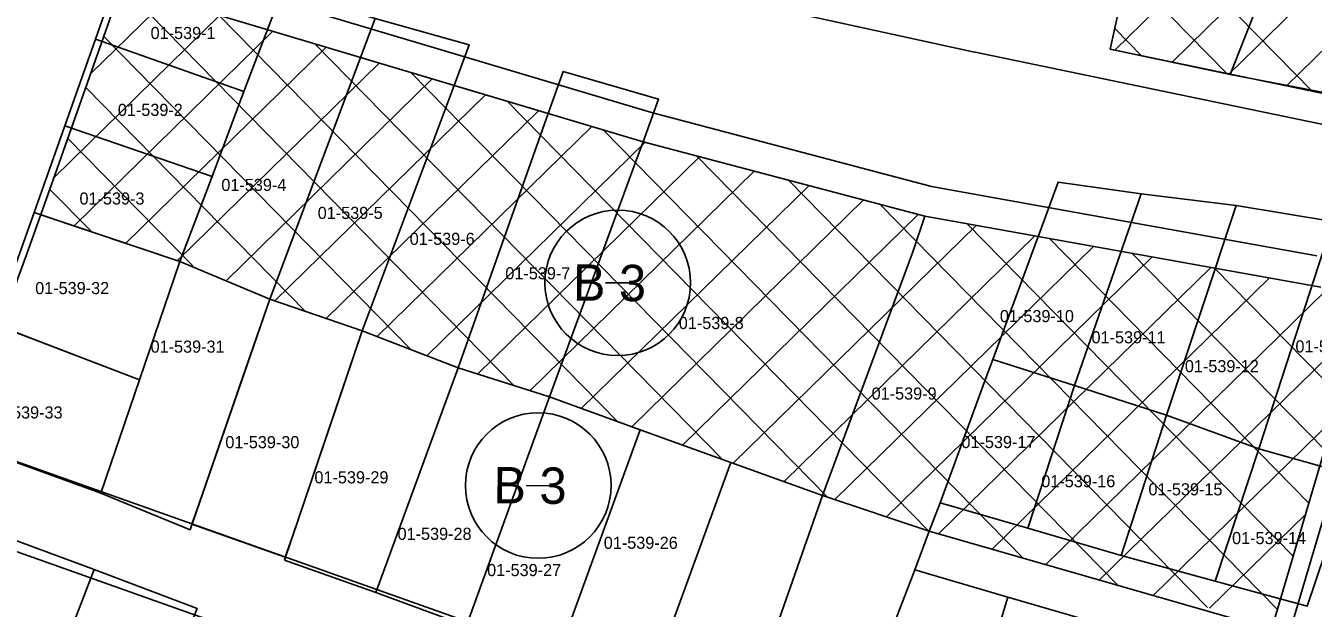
# Model space of a CAD drawing. Extents: x 413946 to 415528, y 4453939 to 4454944.
# Drawn here: x 415070.8 to 415176.9, y 4454376.6 to 4454424.6 of the extents above; entities that cross this region are included whole.
import ezdxf

# ---------------------------------------------------------------- set-up
doc = ezdxf.new("R2010")
doc.units = 0
for name, color, linetype in [('0_KADASTRO', 7, 'Continuous'), ('Level 27', 7, 'Continuous'), ('Level 29', 7, 'Continuous'), ('Level 32', 7, 'Continuous'), ('Level 34', 7, 'Continuous'), ('Level 57', 7, 'Continuous'), ('Level 62', 7, 'Continuous')]:
    doc.layers.add(name, color=color, linetype=linetype)

msp = doc.modelspace()

# ---------------------------------------------------------------- linework, layer by layer
at = {"layer": '0_KADASTRO'}
for points in [[(415160.16, 4454422.69), (415162.75, 4454434.4), (415165.76, 4454447.93), (415177.83, 4454443.03), (415178.24, 4454442.84), (415178.86, 4454442.55), (415176.37, 4454436.61), (415174.78, 4454432.63), (415170.05, 4454420.62)], [(415170.05, 4454420.62), (415174.78, 4454432.63), (415176.37, 4454436.61), (415178.86, 4454442.55), (415187.02, 4454438.74), (415184.58, 4454432.79), (415178.92, 4454418.9)], [(415076.56, 4454423.51), (415079.21, 4454431.05), (415091.94, 4454427.51), (415088.79, 4454419.21)], [(415083.5, 4454405.19), (415086.16, 4454412.19), (415088.79, 4454419.21), (415091.94, 4454427.51), (415099.59, 4454425.23), (415090.92, 4454402.08)], [(415090.92, 4454402.08), (415099.59, 4454425.23), (415107.35, 4454423.05), (415106.1, 4454419.71), (415098.53, 4454399.46)], [(415074.02, 4454416.38), (415076.56, 4454423.51), (415088.79, 4454419.21), (415086.16, 4454412.19)], [(415106.43, 4454396.4), (415113.86, 4454417.39), (415115.09, 4454420.86), (415122.95, 4454418.57), (415121.68, 4454415.05), (415121.13, 4454413.59), (415113.97, 4454394.01)], [(415098.53, 4454399.46), (415106.1, 4454419.71), (415113.86, 4454417.39), (415106.43, 4454396.4)], [(415071.51, 4454409.23), (415074.02, 4454416.38), (415086.16, 4454412.19), (415083.5, 4454405.19)], [(415113.97, 4454394.01), (415121.13, 4454413.59), (415121.68, 4454415.05), (415144.9, 4454408.93), (415143.87, 4454405.91), (415136.45, 4454385.89), (415128.92, 4454388.61), (415121.44, 4454391.29)], [(415150.5, 4454397.11), (415154.24, 4454407.25), (415154.36, 4454407.59), (415155.89, 4454411.73), (415162.73, 4454410.76), (415157.23, 4454394.94)], [(415157.23, 4454394.94), (415162.73, 4454410.76), (415170.55, 4454409.79), (415164.81, 4454392.51)], [(415068.21, 4454400.01), (415071.51, 4454409.23), (415083.5, 4454405.19), (415080.18, 4454395.43)], [(415164.81, 4454392.51), (415170.55, 4454409.79), (415178.51, 4454408.47), (415172.41, 4454389.72)], [(415136.45, 4454385.89), (415143.87, 4454405.91), (415144.9, 4454408.93), (415153.94, 4454407.3), (415154.24, 4454407.25), (415150.5, 4454397.11), (415150.12, 4454396.08), (415146.16, 4454385.28), (415145.24, 4454382.95)], [(415172.41, 4454389.72), (415178.51, 4454408.47), (415186.56, 4454407.48), (415180.05, 4454387.58)], [(415077.01, 4454386.07), (415080.18, 4454395.43), (415083.5, 4454405.19), (415090.92, 4454402.08), (415084.35, 4454383.06)], [(415084.51, 4454383.52), (415085.1, 4454385.22), (415088.71, 4454395.68), (415090.92, 4454402.08), (415098.53, 4454399.46), (415096.35, 4454393.02), (415092.78, 4454382.49), (415092.2, 4454380.79)], [(415068.7, 4454399.82), (415065.19, 4454390.35), (415077.01, 4454386.07), (415080.18, 4454395.43)], [(415092.12, 4454380.54), (415098.53, 4454399.46), (415106.43, 4454396.4), (415099.65, 4454377.88)], [(415099.65, 4454377.88), (415106.43, 4454396.4), (415113.97, 4454394.01), (415107.23, 4454375.45), (415107.12, 4454375.14)], [(415146.16, 4454385.28), (415150.12, 4454396.08), (415150.5, 4454397.11), (415157.23, 4454394.94), (415153.38, 4454383.19)], [(415153.38, 4454383.19), (415157.23, 4454394.94), (415164.81, 4454392.51), (415161.06, 4454380.94)], [(415107.23, 4454375.45), (415113.97, 4454394.01), (415121.44, 4454391.29), (415114.71, 4454372.79)], [(415161.06, 4454380.94), (415164.81, 4454392.51), (415172.41, 4454389.72), (415168.83, 4454378.8)], [(415114.54, 4454372.33), (415114.71, 4454372.79), (415121.44, 4454391.29), (415128.92, 4454388.61), (415122.05, 4454369.73)], [(415168.83, 4454378.8), (415172.41, 4454389.72), (415180.05, 4454387.58), (415176.39, 4454376.74)], [(415122.05, 4454369.73), (415128.92, 4454388.61), (415136.45, 4454385.89), (415129.86, 4454367.05)], [(415129.86, 4454367.05), (415136.45, 4454385.89), (415145.24, 4454382.95), (415144.06, 4454379.75), (415140.81, 4454371.26), (415138.05, 4454364.04)], [(415059.75, 4454375.97), (415062.85, 4454384.81), (415076.46, 4454379.78), (415073.1, 4454371.06)], [(415071.73, 4454367.47), (415073.1, 4454371.06), (415076.46, 4454379.78), (415084.93, 4454376.57), (415080.1, 4454364.35)], [(415140.81, 4454371.26), (415144.06, 4454379.75), (415151.74, 4454377.5), (415149.1, 4454368.79), (415144.42, 4454370.19)], [(415149.1, 4454368.79), (415151.74, 4454377.5), (415167.07, 4454373.03), (415164.65, 4454364.98), (415160.35, 4454365.95), (415156.93, 4454366.72)]]:
    msp.add_lwpolyline(points, close=True, dxfattribs=at)
at = {"layer": 'Level 27'}
msp.add_line((415196.79, 4454415.06), (415160.16, 4454422.69), dxfattribs=at)
for points in [[(415160.16, 4454422.69), (415162.75, 4454434.4), (415165.76, 4454447.93), (415169.01, 4454456.32), (415172.24, 4454464.66), (415174.96, 4454473.23), (415179.19, 4454482.82)], [(415065.21, 4454390.38), (415070.88, 4454405.72), (415073.41, 4454412.84), (415078.7, 4454427.91)], [(415117.21, 4454371.9), (415065.21, 4454390.38)], [(415062.67, 4454383.86), (415095.62, 4454372.15)]]:
    msp.add_lwpolyline(points, dxfattribs=at)
at = {"layer": 'Level 29'}
for points in [[(415078.7, 4454427.91), (415121.68, 4454415.05), (415144.9, 4454408.93), (415177.52, 4454403.06)], [(415180.61, 4454399.02), (415173.46, 4454374.82), (415172.45, 4454371.28)]]:
    msp.add_lwpolyline(points, dxfattribs=at)
at = {"layer": 'Level 32'}
for p, q in [((415120.59, 4454403.41), (415118.59, 4454403.43)), ((415114.04, 4454386.69), (415112.04, 4454386.71))]:
    msp.add_line(p, q, dxfattribs=at)
for centre in [(415119.59, 4454403.42), (415113.04, 4454386.7)]:
    msp.add_circle(centre, 6, dxfattribs=at)
at = {"layer": 'Level 34'}
for p, q in [((415160.55, 4454422.61), (415179.15, 4454440.84)), ((415165.26, 4454421.63), (415183.73, 4454439.72)), ((415169.98, 4454420.65), (415188.3, 4454438.61)), ((415174.69, 4454419.67), (415192.88, 4454437.49)), ((415176.81, 4454419.22), (415162.6, 4454433.73)), ((415169.78, 4454420.69), (415161.57, 4454429.07)), ((415111.07, 4454394.93), (415078.79, 4454427.88)), ((415076.16, 4454420.66), (415082.42, 4454426.79)), ((415073.16, 4454412.12), (415086.8, 4454425.49)), ((415119.57, 4454391.97), (415086.71, 4454425.51)), ((415074.79, 4454408.12), (415091.18, 4454424.17)), ((415162.74, 4454422.15), (415160.54, 4454424.4)), ((415102.56, 4454397.9), (415077.24, 4454423.75)), ((415128.22, 4454388.86), (415094.63, 4454423.14)), ((415079.05, 4454406.69), (415095.56, 4454422.87)), ((415083.31, 4454405.27), (415099.94, 4454421.55)), ((415136.88, 4454385.74), (415102.55, 4454420.77)), ((415087.32, 4454403.59), (415104.31, 4454420.25)), ((415093.86, 4454401.07), (415075.76, 4454419.54)), ((415091.34, 4454401.94), (415108.69, 4454418.94)), ((415095.57, 4454400.48), (415113.07, 4454417.62)), ((415145.19, 4454382.97), (415110.47, 4454418.4)), ((415099.8, 4454399.02), (415117.45, 4454416.32)), ((415153, 4454380.71), (415118.4, 4454416.03)), ((415084.58, 4454404.83), (415074.29, 4454415.33)), ((415103.86, 4454397.4), (415121.83, 4454415.01)), ((415108.04, 4454395.89), (415126.34, 4454413.82)), ((415160.8, 4454378.47), (415126.1, 4454413.88)), ((415112.35, 4454394.52), (415130.84, 4454412.64)), ((415116.56, 4454393.04), (415135.35, 4454411.45)), ((415168.19, 4454376.64), (415133.65, 4454411.9)), ((415076.22, 4454407.65), (415072.8, 4454411.13)), ((415120.74, 4454391.54), (415139.85, 4454410.26)), ((415173.95, 4454376.48), (415141.2, 4454409.91)), ((415124.93, 4454390.04), (415144.35, 4454409.07)), ((415129.11, 4454388.54), (415149.14, 4454408.17)), ((415175.25, 4454380.87), (415148.36, 4454408.31)), ((415133.29, 4454387.03), (415153.97, 4454407.3)), ((415176.54, 4454385.26), (415155.16, 4454407.08)), ((415137.48, 4454385.54), (415158.8, 4454406.43)), ((415141.74, 4454384.12), (415163.63, 4454405.56)), ((415177.84, 4454389.65), (415161.96, 4454405.86)), ((415146.03, 4454382.72), (415168.46, 4454404.69)), ((415150.45, 4454381.45), (415173.29, 4454403.83)), ((415179.14, 4454394.04), (415168.76, 4454404.64)), ((415154.87, 4454380.18), (415177.82, 4454402.67)), ((415159.28, 4454378.91), (415180.27, 4454399.46)), ((415163.7, 4454377.63), (415178.61, 4454392.24)), ((415168.35, 4454376.58), (415176.28, 4454384.35))]:
    msp.add_line(p, q, dxfattribs=at)
at = {"layer": 'Level 57'}
msp.add_lwpolyline([(415072.06, 4454409.04), (415083.5, 4454405.19), (415090.92, 4454402.08), (415098.53, 4454399.46), (415106.43, 4454396.4), (415113.97, 4454394.01), (415121.44, 4454391.29), (415128.92, 4454388.61), (415136.45, 4454385.89), (415145.24, 4454382.95), (415173.46, 4454374.82)], dxfattribs=at)
at = {"layer": 'Level 62'}
for p, q in [((415148.99, 4454422.46), (415117.67, 4454429.3)), ((415205.58, 4454410.68), (415149.04, 4454422.45))]:
    msp.add_line(p, q, dxfattribs=at)
for points in [[(415078.4, 4454430.61), (415122.36, 4454417.46), (415145.44, 4454411.37), (415177.2, 4454405.66)], [(415181.88, 4454398.03), (415174.9, 4454374.4), (415174.01, 4454371.27)]]:
    msp.add_lwpolyline(points, dxfattribs=at)
msp.add_arc((415150.05, 4454427.35), 5, 257.6881, 258.2399, dxfattribs=at)

# ---------------------------------------------------------------- texts
at = {"layer": '0_KADASTRO'}
for s, p in [('01-539-1', (415081.1, 4454423.53)), ('01-539-2', (415078.4, 4454417.19)), ('01-539-4', (415086.93, 4454411)), ('01-539-3', (415075.24, 4454409.88)), ('01-539-5', (415094.87, 4454408.69)), ('01-539-6', (415102.45, 4454406.55)), ('01-539-7', (415110.33, 4454403.71)), ('01-539-32', (415071.59, 4454402.49)), ('01-539-8', (415124.62, 4454399.61)), ('01-539-10', (415151.08, 4454400.18)), ('01-539-31', (415081.1, 4454397.66)), ('01-539-11', (415158.63, 4454398.43)), ('01-539-13', (415175.43, 4454397.68)), ('01-539-12', (415166.32, 4454396.05)), ('01-539-9', (415140.51, 4454393.79)), ('01-539-33', (415067.75, 4454392.23)), ('01-539-30', (415087.26, 4454389.78)), ('01-539-17', (415147.91, 4454389.79)), ('01-539-29', (415094.6, 4454386.88)), ('01-539-16', (415154.49, 4454386.56)), ('01-539-15', (415163.32, 4454385.89)), ('01-539-28', (415101.45, 4454382.22)), ('01-539-14', (415170.21, 4454381.87)), ('01-539-26', (415118.44, 4454381.48)), ('01-539-27', (415108.83, 4454379.23))]:
    msp.add_text(s, height=1, dxfattribs=at).set_placement(p)
at = {"layer": 'Level 32'}
for p in [(415115.89, 4454401.96), (415109.34, 4454385.24)]:
    msp.add_text('B 3', height=3, rotation=359.4141, dxfattribs=at).set_placement(p)

doc.saveas('drawing.dxf')
